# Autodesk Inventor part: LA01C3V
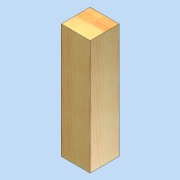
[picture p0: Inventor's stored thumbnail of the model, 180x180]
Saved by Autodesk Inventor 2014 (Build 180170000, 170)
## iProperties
Created: 2011-04
Part Number: LA01C3V
Document SubType Name: Modeling
Designer: david.appleford
Density: 0.44 g/cm^3
Description: Lug 0.25w End 1 Slot
Mass: 549.331 g
Surface Area: 826.88 cm^2
Volume: 1248.48 cm^3
Cost Center: £6.00
Material: 000 Redwood
Appearance: Wood (Pine)
Justset: False
Author: david.appleford
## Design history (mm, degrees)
sketch "Sketch1"
  geometry: L1 (0, 0)-(68, 0); L2 (68, 0)-(68, 68); L3 (68, 68)-(0, 68); L4 (0, 68)-(0, 0)
  constraints: 8 end point, 2 parallel, 1 horizontal, 1 perpendicular
  dimensions: "d0" = 68 distance between parallel lines of L2 L4 (= t); "d1" = 68 distance between parallel lines of L1 L3 (= t)
extrude "Extrusion1" new body sketch "Sketch1" distance "d2" = 305 (= 0.25 x w); taper "d3" = 0 deg
feature "Move Face1" dims "d4" = 35
body "Solid1"
other parameters: "t" = 68 [user parameter; used in 2 equation terms], "Cl" = 2 [user parameter]
